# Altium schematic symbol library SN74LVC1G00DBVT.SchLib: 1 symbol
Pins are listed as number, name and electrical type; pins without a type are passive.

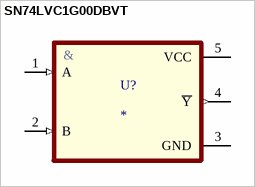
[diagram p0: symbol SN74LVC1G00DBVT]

## SN74LVC1G00DBVT
designator U?
NAND IC 1 canal SOT-23-5; MF: Texas Instruments; MP: SN74LVC1G00DBV
footprint SOT23-5
pins: 1 A (in), 2 B (in), 3 GND, 4 ~{Y} (out), 5 VCC (power)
